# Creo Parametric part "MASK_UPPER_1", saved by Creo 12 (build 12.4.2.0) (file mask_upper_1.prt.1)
Units: Custom; MM, KILOGRAM, SECS

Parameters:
  PTC_WM_ITERATION = "0"
  PTC_WM_VERSION = "-.0"
  PTC_WM_LIFECYCLE_STATE = "In Work"
  PTC_WM_LIFECYCLE = "MO_CADDocument"
  PTC_WM_CREATED_BY = "Maximilian Roepper (Z0017RMS: MO)"
  PTC_WM_CREATED_ON = "18-Sep-26 11:36:42 AM"
  PTC_WM_MODIFIED_BY = "Maximilian Roepper (Z0017RMS: MO)"
  PTC_WM_MODIFIED_ON = "18-Sep-26 11:36:46 AM"
  PDMLINKNUMBER = "PDM000071455333"
  PTC_WM_NAME = "mask_upper_1.prt"
  PTC_WM_NUMBER = "PDM000071455333"

Other parameters: WEIGHT, WEIGHT_FACTOR, WEIGHT_ADD, _MASS_TEMP, _DIFF_TEMP, MC_ERRORS, SUPPLIER

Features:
  1. coordinate system
  2. datum plane "PRT_YZ"
  3. datum plane "PRT_XY"
  4. datum plane "PRT_XZ"
  5. coordinate system
  6. datum axis
  7. datum axis
  8. datum axis
  9. coordinate system
  10. imported feature
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
Other named items: PRT, SIEMENS_MO, DRW_VIEW_ORG, PRT_X, PRT_Y, PRT_Z, CS0, ROUGH_GROB

Layers: 00_STD_CSYS-KSYS, 01_STD_PLANES-EBENEN, 02_STD_AXES-ACHSEN, 03_STD_CSYS-KSYS, 24_IMPORT_FEAT-IMPORT_KE

Surfaces: 95 plane, 44 cylinder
